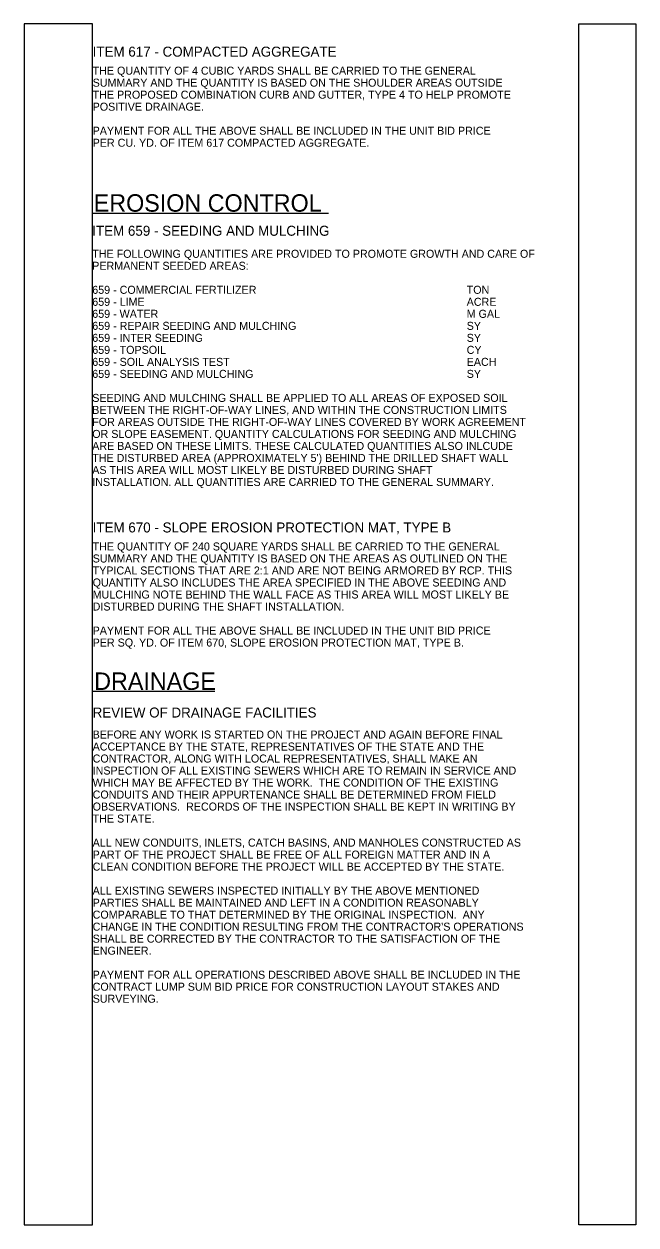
# Model space of a CAD drawing. Extents: x -9.7 to 42.8, y 0 to 45.4.
# Drawn here: x 21.3 to 32, y 24.42 to 45.42 of the extents above; entities that cross this region are included whole.
import ezdxf

# ---------------------------------------------------------------- set-up
doc = ezdxf.new("R2010")
doc.units = 0
for name, color, linetype in [('Default', 7, 'Continuous'), ('SC_Scratch1', 7, 'Continuous'), ('TX_P_1', 7, 'Continuous')]:
    doc.layers.add(name, color=color, linetype=linetype)

msp = doc.modelspace()

# ---------------------------------------------------------------- linework, layer by layer
at = {"layer": 'Default'}
for p, q in [((22.5, 42.114), (26.621, 42.114)), ((22.508, 33.751), (24.634, 33.751))]:
    msp.add_line(p, q, dxfattribs=at)
at = {"layer": 'SC_Scratch1'}
for p, q in [((21.3, 45.42), (21.3, 24.42)), ((22.5, 45.42), (21.3, 45.42)), ((22.5, 24.42), (22.5, 45.42)), ((31, 24.42), (31, 45.42)), ((31, 45.42), (32, 45.42)), ((32, 45.42), (32, 24.42)), ((21.3, 24.42), (22.5, 24.42)), ((32, 24.42), (31, 24.42))]:
    msp.add_line(p, q, dxfattribs=at)

# ---------------------------------------------------------------- texts
at = {"layer": 'TX_P_1'}
for s, height, p in [('ITEM 617 - COMPACTED AGGREGATE', 0.175, (22.5, 44.849)), ('THE QUANTITY OF 4 CUBIC YARDS SHALL BE CARRIED TO THE GENERAL ', 0.14, (22.5, 44.534)), ('SUMMARY AND THE QUANTITY IS BASED ON THE SHOULDER AREAS OUTSIDE ', 0.14, (22.5, 44.324)), ('THE PROPOSED COMBINATION CURB AND GUTTER, TYPE 4 TO HELP PROMOTE', 0.14, (22.5, 44.114)), ('POSITIVE DRAINAGE.', 0.14, (22.5, 43.904)), ('PAYMENT FOR ALL THE ABOVE SHALL BE INCLUDED IN THE UNIT BID PRICE ', 0.14, (22.5, 43.484)), ('PER CU. YD. OF ITEM 617 COMPACTED AGGREGATE.', 0.14, (22.5, 43.274)), ('EROSION CONTROL', 0.30475, (22.519, 42.138)), ('ITEM 659 - SEEDING AND MULCHING', 0.175, (22.493, 41.717)), ('THE FOLLOWING QUANTITIES ARE PROVIDED TO PROMOTE GROWTH AND CARE OF ', 0.14, (22.493, 41.332)), ('PERMANENT SEEDED AREAS:', 0.14, (22.493, 41.122)), ('659 - COMMERCIAL FERTILIZER', 0.14, (22.493, 40.702)), ('TON', 0.14, (29.04, 40.702)), ('659 - LIME', 0.14, (22.493, 40.492)), ('ACRE', 0.14, (29.04, 40.492)), ('659 - WATER', 0.14, (22.493, 40.282)), ('M GAL', 0.14, (29.04, 40.282)), ('659 - REPAIR SEEDING AND MULCHING', 0.14, (22.493, 40.072)), ('SY', 0.14, (29.04, 40.072)), ('659 - INTER SEEDING', 0.14, (22.493, 39.862)), ('SY', 0.14, (29.04, 39.862)), ('659 - TOPSOIL', 0.14, (22.493, 39.652)), ('CY', 0.14, (29.04, 39.652)), ('659 - SOIL ANALYSIS TEST', 0.14, (22.493, 39.442)), ('EACH', 0.14, (29.04, 39.442)), ('659 - SEEDING AND MULCHING', 0.14, (22.493, 39.232)), ('SY', 0.14, (29.04, 39.232)), ('SEEDING AND MULCHING SHALL BE APPLIED TO ALL AREAS OF EXPOSED SOIL ', 0.14, (22.493, 38.812)), ('BETWEEN THE RIGHT-OF-WAY LINES, AND WITHIN THE CONSTRUCTION LIMITS ', 0.14, (22.493, 38.602)), ('FOR AREAS OUTSIDE THE RIGHT-OF-WAY LINES COVERED BY WORK AGREEMENT ', 0.14, (22.493, 38.392)), ('OR SLOPE EASEMENT. QUANTITY CALCULATIONS FOR SEEDING AND MULCHING ', 0.14, (22.493, 38.182)), ('ARE BASED ON THESE LIMITS. THESE CALCULATED QUANTITIES ALSO INLCUDE ', 0.14, (22.493, 37.972)), ("THE DISTURBED AREA (APPROXIMATELY 5') BEHIND THE DRILLED SHAFT WALL ", 0.14, (22.493, 37.762)), ('AS THIS AREA WILL MOST LIKELY BE DISTURBED DURING SHAFT ', 0.14, (22.493, 37.552)), ('INSTALLATION. ALL QUANTITIES ARE CARRIED TO THE GENERAL SUMMARY.', 0.14, (22.493, 37.342)), ('ITEM 670 - SLOPE EROSION PROTECTION MAT, TYPE B', 0.175, (22.5, 36.529)), ('THE QUANTITY OF 240 SQUARE YARDS SHALL BE CARRIED TO THE GENERAL ', 0.14, (22.5, 36.214)), ('SUMMARY AND THE QUANTITY IS BASED ON THE AREAS AS OUTLINED ON THE ', 0.14, (22.5, 36.004)), ('TYPICAL SECTIONS THAT ARE 2:1 AND ARE NOT BEING ARMORED BY RCP. THIS ', 0.14, (22.5, 35.794)), ('QUANTITY ALSO INCLUDES THE AREA SPECIFIED IN THE ABOVE SEEDING AND  ', 0.14, (22.5, 35.584)), ('MULCHING NOTE BEHIND THE WALL FACE AS THIS AREA WILL MOST LIKELY BE ', 0.14, (22.5, 35.374)), ('DISTURBED DURING THE SHAFT INSTALLATION. ', 0.14, (22.5, 35.164)), ('PAYMENT FOR ALL THE ABOVE SHALL BE INCLUDED IN THE UNIT BID PRICE ', 0.14, (22.5, 34.744)), ('PER SQ. YD. OF ITEM 670, SLOPE EROSION PROTECTION MAT, TYPE B.', 0.14, (22.5, 34.534)), ('DRAINAGE', 0.3047, (22.527, 33.776)), ('REVIEW OF DRAINAGE FACILITIES', 0.175, (22.5, 33.293)), ('BEFORE ANY WORK IS STARTED ON THE PROJECT AND AGAIN BEFORE FINAL ', 0.14, (22.5, 32.926)), ('ACCEPTANCE BY THE STATE, REPRESENTATIVES OF THE STATE AND THE ', 0.14, (22.5, 32.716)), ('CONTRACTOR, ALONG WITH LOCAL REPRESENTATIVES, SHALL MAKE AN ', 0.14, (22.5, 32.506)), ('INSPECTION OF ALL EXISTING SEWERS WHICH ARE TO REMAIN IN SERVICE AND ', 0.14, (22.5, 32.296)), ('WHICH MAY BE AFFECTED BY THE WORK.  THE CONDITION OF THE EXISTING ', 0.14, (22.5, 32.086)), ('CONDUITS AND THEIR APPURTENANCE SHALL BE DETERMINED FROM FIELD ', 0.14, (22.5, 31.876)), ('OBSERVATIONS.  RECORDS OF THE INSPECTION SHALL BE KEPT IN WRITING BY ', 0.14, (22.5, 31.666)), ('THE STATE.', 0.14, (22.5, 31.456)), ('ALL NEW CONDUITS, INLETS, CATCH BASINS, AND MANHOLES CONSTRUCTED AS  ', 0.14, (22.5, 31.036)), ('PART OF THE PROJECT SHALL BE FREE OF ALL FOREIGN MATTER AND IN A ', 0.14, (22.5, 30.826)), ('CLEAN CONDITION BEFORE THE PROJECT WILL BE ACCEPTED BY THE STATE.', 0.14, (22.5, 30.616)), ('ALL EXISTING SEWERS INSPECTED INITIALLY BY THE ABOVE MENTIONED ', 0.14, (22.5, 30.196)), ('PARTIES SHALL BE MAINTAINED AND LEFT IN A CONDITION REASONABLY ', 0.14, (22.5, 29.986)), ('COMPARABLE TO THAT DETERMINED BY THE ORIGINAL INSPECTION.  ANY ', 0.14, (22.5, 29.776)), ("CHANGE IN THE CONDITION RESULTING FROM THE CONTRACTOR'S OPERATIONS ", 0.14, (22.5, 29.566)), ('SHALL BE CORRECTED BY THE CONTRACTOR TO THE SATISFACTION OF THE ', 0.14, (22.5, 29.356)), ('ENGINEER.', 0.14, (22.5, 29.146)), ('PAYMENT FOR ALL OPERATIONS DESCRIBED ABOVE SHALL BE INCLUDED IN THE ', 0.14, (22.5, 28.726)), ('CONTRACT LUMP SUM BID PRICE FOR CONSTRUCTION LAYOUT STAKES AND ', 0.14, (22.5, 28.516)), ('SURVEYING.', 0.14, (22.5, 28.306))]:
    msp.add_text(s, height=height, dxfattribs=at).set_placement(p)

doc.saveas('drawing.dxf')
